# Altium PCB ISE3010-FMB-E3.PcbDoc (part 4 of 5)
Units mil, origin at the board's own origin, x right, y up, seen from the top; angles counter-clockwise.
Board outline 7874.02 x 2362.2 mil, 4 copper layers (Top Layer, MidLayer1, MidLayer2, Bottom Layer), stack 55.6 mil thick; 507 components, 331 nets, 1707 pads, 610 vias.
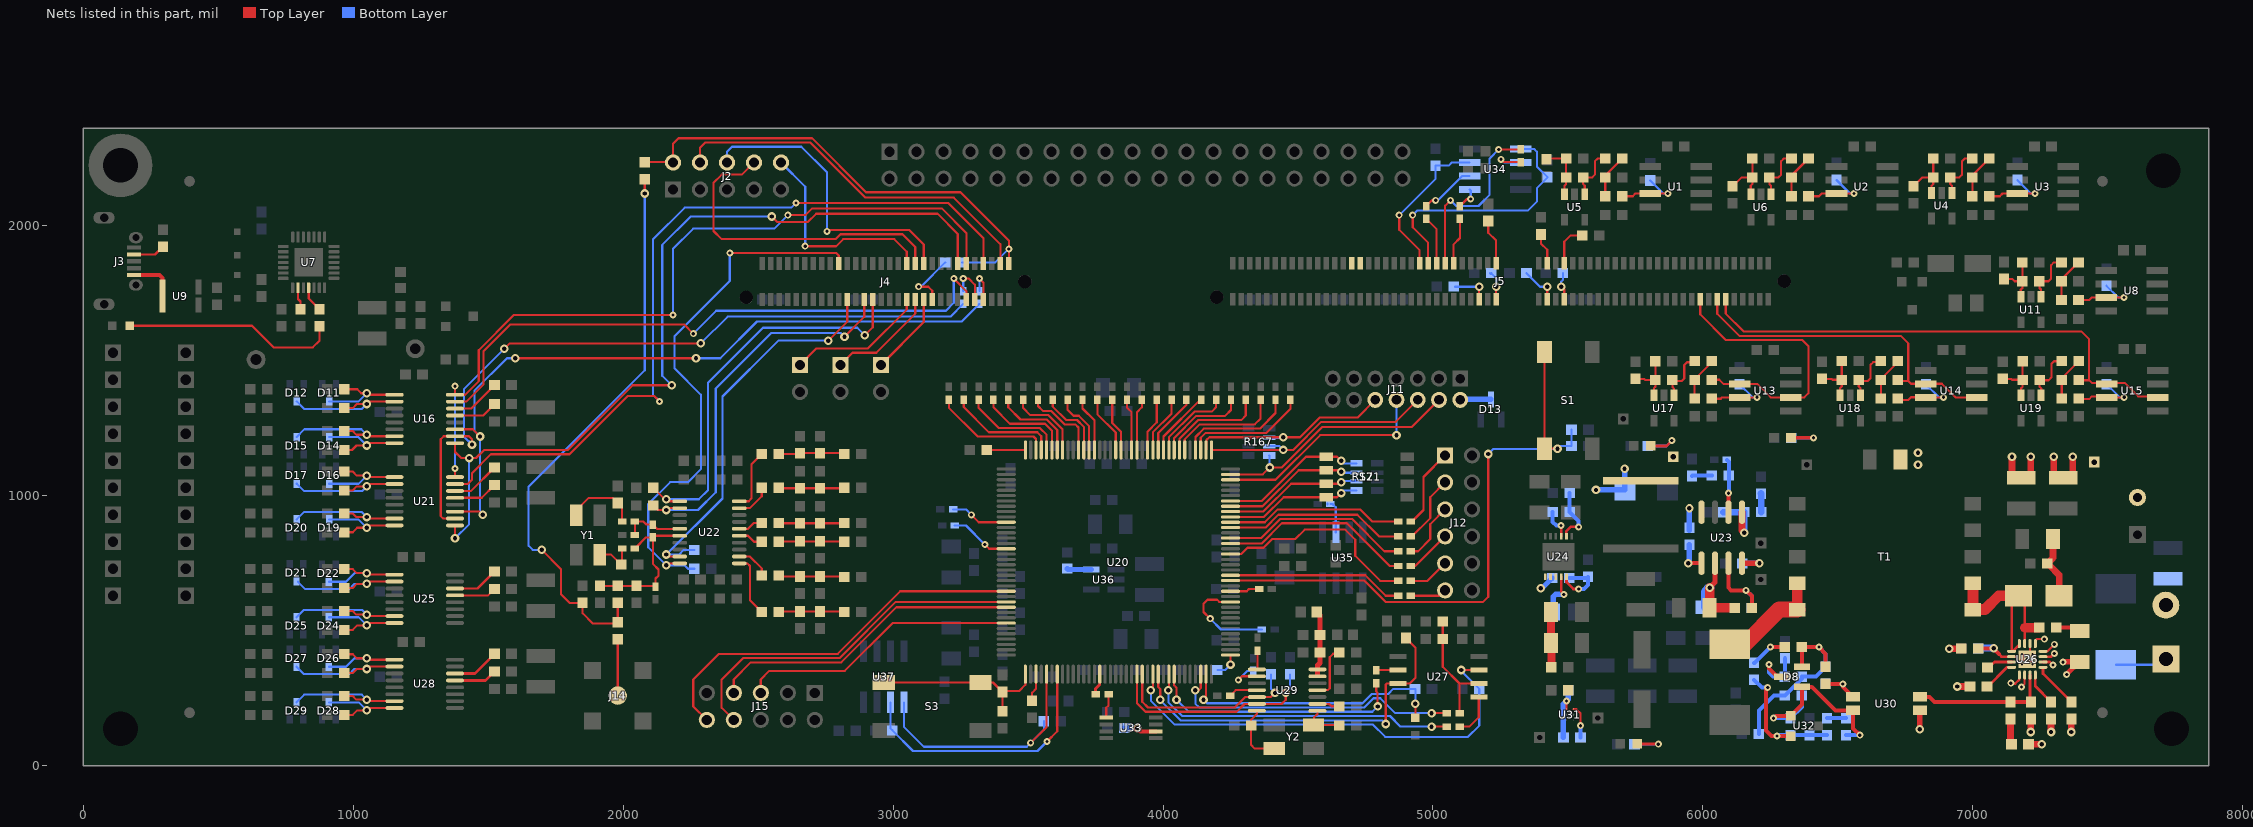
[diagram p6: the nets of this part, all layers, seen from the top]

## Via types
v1: diameter 32, hole 16, Top Layer to Bottom Layer, tented both sides, 495 vias
v2: diameter 26, hole 12, Top Layer to Bottom Layer, tented both sides, 104 vias
v3: diameter 20, hole 8, Top Layer to Bottom Layer, tented both sides, 10 vias
v4: diameter 30, hole 16, Top Layer to Bottom Layer, tented both sides, 1 vias

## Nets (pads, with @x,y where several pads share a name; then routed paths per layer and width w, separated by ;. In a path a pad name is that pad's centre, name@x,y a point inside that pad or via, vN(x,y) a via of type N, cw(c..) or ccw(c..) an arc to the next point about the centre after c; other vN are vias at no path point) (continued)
GND: C41.1 C48.2 C49.2 C50.2 C90.2 C98.2 C103.2 C109.2 C146.2 J13.2 R131.1 R150.2 R151.2 TP5.1 U26.5 U26.6 U26.10 U26.11 U26.12 U26.13 U26.14 U26.17 U30.3 | length 1218.7
  Top Layer w8: v2(7180,292) 7192.09,304.09 U26.6@7192.09,336.46 ; v3(7201.93,394.53) 7211.77,404.37 U26.14@7211.77,452.6 ; U26.13@7232,453.14 7232,464 7238,470 7259,470 7260,469 v2(7265,469) ; U26.12@7260,424.06 7277.06,424.06 7303,450 v2(7302,450)
  Top Layer w9: v2(7141,306) 7143,304 7157,304 7172.4,319.4 U26.5@7172.4,336.46 ; U26.11@7260,404.37 7290.37,404.37 v2(7302,416)
  Top Layer w10: U26.10@7260,384.68 7285.31,384.68 v2(7297,373)
  Top Layer w20: v1(6804.02,135.98) U30.3@6804.02,205 ; v2(7334,384) 7338,384 7338.91,384.91 R131.1@7396,384.91 7392.91,384.91 v2@7348,340
  Top Layer w25: v1(6913,434) 6956.5,434 C90.2@6957.5,435 ; v1(6942,294) C98.2@6990.5,294 ; v1(7145,1145) 7145,1070 7180,1070 C48.2@7180,1067.09 ; C109.2@7206.5,80 v1(7255,80) ; v1(7215,125) C103.2@7215,173.5 ; C48.2@7215,1070 v1(7215,1145) ; v1(7290,125) R150.2@7290,173.5 ; v1(7300,1145) 7300,1070 7335,1070 C49.2@7335,1067.09 ; v1(7365,125) R151.2@7365,173.5 ; C49.2@7370,1070 v1(7370,1145)
  other v1: 6797,1115 6797,1160
  other v2: 7348,338
  other v3: 7182.24,374.84 7221.61,374.84 7182.24,414.21 7221.61,414.21
GPIO1: J2.10 J4.145 | length 797
  Top Layer w8: v2(2674.5,1925) 2789,1925 2815,1951 3004.2,1951 3050.92,1904.28 J4.145@3050.92,1860.93
  Bottom Layer w8: J2.10@2585,2235 2674.5,2145.5 v2(2674.5,1925)
GPIO1_FPGA: J15.7 U20.27 | length 1170.1
  Top Layer w8: J15.7@2410,270 2410,320 2473.2,383.2 2807.89,383.2 3012.21,587.52 U20.27@3419.29,587.52
GPIO2: J2.6 J4.141 | length 1128.8
  Top Layer w8: v2(2755,1980) 2760,1985 3060,1985 3113.91,1931.09 J4.141@3113.91,1860.93
  Bottom Layer w8: J2.6@2385,2235 2385,2275 2403.4,2293.4 2660,2293.4 2755,2198.4 v2(2755,1980)
GPIO2_FPGA: J15.8 U20.26 | length 1341.9
  Top Layer w8: J15.8@2410,170 2365,215 2365,320 2444,399 2801.34,399 3009.55,607.2 U20.26@3419.29,607.2
GPIO3: J2.8 J4.143 | length 1207.9
  Top Layer w8: J2.8@2485,2235 2440,2190 2365,2190 2335,2160 2335,1981 2365,1951 2786.8,1951 2805,1969.2 3035,1969.2 3082.42,1921.78 J4.143@3082.42,1860.93
GPIO3_FPGA: J15.10 U20.24 | length 1465.3
  Top Layer w8: J15.10@2310,170 2260,220 2260,320 2354.8,414.8 2794.8,414.8 3026.57,646.57 U20.24@3419.29,646.57
I2C_SCL: J4.161 R208.2 U22.10 | length 2028.9
  Top Layer w8: v1(2160,742.74) 2167.1,749.84 U22.10@2209.76,749.84 ; v2(2395,1900) 2789.5,1900 2798.95,1890.55 J4.161@2798.95,1860.93
  Bottom Layer w8: R208.2@2263.5,730 2240.02,730 2227.28,742.74 v1(2160,742.74) 2093,809.74 2093,970 2174,1051 2240,1051 2288,1099 2288,1375 2190,1473 2190,1591 2395,1796 v2(2395,1900)
I2C_SCL_2: J5.91
I2C_SCL_FPGA: R203.1 U20.43 U37.6 | length 990.8
  Top Layer w8: v2(3570,90) 3608.27,128.27 U20.43@3608.27,339.49
  Bottom Layer w8: U37.6@2990,235 2990,138.78 R203.1@2997.36,131.42 3073.78,55 3535,55 v2(3570,90)
I2C_SDA: J4.160 R207.2 U22.9 | length 1494.1
  Top Layer w8: v1(2160,782.54) 2167.1,775.43 U22.9@2209.76,775.43 ; v1(2760,1575) 2830.45,1645.45 J4.160@2830.45,1727.07
  Bottom Layer w8: R207.2@2263.5,800 2225,800 2207.54,782.54 v1(2160,782.54) 2368,990.54 2368,1368 2575,1575 v1(2760,1575)
I2C_SDA_2: J5.89
I2C_SDA_FPGA: R201.1 U20.41 U37.5 | length 975.6
  Top Layer w8: v2(3510,85) 3568.9,143.9 U20.41@3568.9,339.49
  Bottom Layer w8: U37.5@3040,235 3040,145 3114.2,70.8 3495.8,70.8 v2(3510,85) 3558.5,133.5 R201.1@3558.5,165
MCU_DAC_ENABLE-1: J4.132 U16.15 | length 2286.6
  Top Layer w8: U16.15@1377.2,1348.98 1418.98,1348.98 1482.2,1412.2 1482.2,1534.86 1582.34,1635 2226,1635 v2(2260,1601) ; v2(3224.93,1805) 3271.39,1758.53 J4.132@3271.39,1727.07
  Bottom Layer w8: v2(2260,1601) 2344.8,1685.8 3195.8,1685.8 3224.93,1714.93 v2(3224.93,1805)
MCU_DAC_ENABLE-2: J4.127 U21.15 | length 2953.9
  Top Layer w8: U21.15@1377.2,1043.98 1423.98,1043.98 1440,1060 1440,1084.2 1510,1154.2 1801.54,1154.2 2017.34,1370 2115,1370 v2(2135,1350) ; v2(2640,2085) 3204.39,2085 3334.39,1955 J4.127@3334.39,1860.93
  Bottom Layer w8: v2(2135,1350) 2110,1375 2110,1950 2227.8,2067.8 2622.8,2067.8 v2(2640,2085)
MCU_DAC_SCK: R165.1 U16.10 U21.10 | length 2685.5
  Top Layer w8: U21.10@1377.2,916.02 1333.03,916.02 1324.06,925 1324.06,1210.08 1335,1221.02 U16.10@1377.2,1221.02 1428.98,1221.02 1440,1210 v1(1440,1190) ; v1(1560,1545) 1580,1565 v1(2288,1565)
  Bottom Layer w8: v1(1440,1190) 1410,1220 1410,1395 v1(1560,1545) ; v1(2288,1565) 2387,1664 3212.62,1664 R165.1@3260,1711.38
MCU_DAC_SDI: R164.1 U16.11 U21.11 | length 2687.8
  Top Layer w8: U21.11@1377.2,941.61 1468.39,941.61 v1(1480,930) ; U16.11@1377.2,1246.61 1443.39,1246.61 v1(1470,1220) ; v1(1600,1510) v1(2270,1510)
  Bottom Layer w8: v1(1480,930) 1470,940 v1(1470,1220) 1448.98,1241.02 1448.98,1388.98 1570,1510 v1(1600,1510) ; v1(2270,1510) 2360,1510 2496,1646 3254.62,1646 R164.1@3320,1711.38
MCU_DAC_SYNC: J4.133 U16.9 U21.9 | length 3156.9
  Top Layer w8: v1(1377.2,842.8) U21.9@1377.2,890.43 ; U16.9@1377.2,1195.43 1377.2,1162.8 1400,1140 v1(1429.32,1140) 1455,1140 1485,1170 1795,1170 2035,1410 v1(2180,1410) ; v1(2550,2035) 2570,2015 2685,2015 2715,2045 3165,2045 3239.9,1970.1 J4.133@3239.9,1860.93
  Bottom Layer w8: v1(1377.2,842.8) 1429.32,894.91 v1(1429.32,1140) ; v1(2180,1410) 2145,1445 2145,1930 2250,2035 v1(2550,2035)
MCU_LDAC: J4.131 U16.16 U21.16 | length 2910.4
  Top Layer w8: U21.16@1377.2,1069.57 v2(1377.2,1101.46) ; v2(1377.2,1406.46) U16.16@1377.2,1374.57 1414.57,1374.57 1465,1425 1465,1540 1595,1670 v2(2185,1670) ; v2(2610,2040) 2675,2040 2700,2065 3180,2065 3271.39,1973.61 J4.131@3271.39,1860.93
  Bottom Layer w8: v2(1377.2,1101.46) v2(1377.2,1406.46) ; v2(2185,1670) 2185,1915 2260,1990 2560,1990 v2(2610,2040)
MCU_SRAM_CS: J5.73 R157.1 U34.1 | length 964.8
  Top Layer w8: v2(4925,2040) 4925,1995 4982.28,1937.72 J5.73@4982.28,1861.93
  Bottom Layer w8: v2(4925,2040) 4942.8,2057.8 5352.8,2057.8 5385,2090 5385,2140.12 R157.1@5425,2180.12 5385,2220.12 5385,2275 5375,2285 U34.1@5325,2285
MCU_SRAM_HOLD: J5.75 R156.1 U34.7 | length 579.6
  Top Layer w8: v2(4875,2040) 4875,1985.79 4950.79,1910 J5.75@4950.79,1861.93
  Bottom Layer w8: v2(4875,2040) 5010,2175 R156.1@5010,2223.5 5058.5,2223.5 5070,2235 U34.7@5136,2235
MCU_SRAM_SCLK: R19.2 U34.6 | length 207.1
  Top Layer w8: R19.2@4975,2073.62 4996.38,2095 v2(5010,2095)
  Bottom Layer w8: v2(5010,2095) 5019,2095 5109,2185 U34.6@5136,2185
MCU_SRAM_SDI: R20.2 U34.5 | length 87.6
  Top Layer w8: R20.2@5100,2073.62 5126.38,2100 v2(5140,2100)
  Bottom Layer w8: U34.5@5136,2135 5140,2131 v2(5140,2100)
MCU_SRAM_SDO: J5.69 R1.2 | length 676.2
  Top Layer w8: J5.69@5045.28,1861.93 5045.28,2075.28 v2(5065,2095) ; v2(5243.62,2283.62) R1.2@5325,2283.62
  Bottom Layer w8: v2(5065,2095) 5086.4,2073.6 5168.6,2073.6 5210,2115 5210,2250 v2(5243.62,2283.62)
NetC6_1: C6.1 R5.1 R15.2 | length 166.1
  Top Layer w8: R15.2@5638.5,2110 C6.1@5638.5,2180 5638.5,2187.01 R5.1@5701.5,2250
NetC7_1: C7.1 R6.1 R16.2 | length 166.1
  Top Layer w8: R16.2@6328.5,2110 C7.1@6328.5,2180 6328.5,2187.01 R6.1@6391.5,2250
NetC8_1: C8.1 R7.1 R17.2 | length 166.1
  Top Layer w8: R17.2@6998.5,2110 C8.1@6998.5,2180 6998.5,2187.01 R7.1@7061.5,2250
NetC16_1: C16.1 R26.1 R28.2 | length 166.1
  Top Layer w8: R28.2@7328.82,1725 C16.1@7328.82,1795 7328.82,1802.01 R26.1@7391.81,1865
NetC29_1: C29.1 R32.1 R69.2 | length 166.1
  Top Layer w8: R69.2@5969.5,1355 5969.5,1425 5969.5,1432.01 R32.1@6032.5,1495
NetC30_1: C30.1 R33.1 R70.2 | length 166.1
  Top Layer w8: R70.2@6659.5,1355.47 6659.5,1425.47 6659.5,1432.48 R33.1@6722.5,1495.47
NetC31_1: C31.1 R34.1 R71.2 | length 166.1
  Top Layer w8: R71.2@7329.5,1358.54 7329.5,1428.54 7329.5,1435.55 R34.1@7392.5,1498.54
NetC42_2: C42.2 R75.2 R76.1 R79.2 | length 244.9
  Top Layer w8: R79.2@2576.5,1155 2651.5,1155 R75.2@2655,1158.5 R76.1@2730,1158.5 2815,1158.5 C42.2@2818.5,1155
NetC55_1: C55.1 R93.1 Y1.3 | length 274.3
  Top Layer w8: Y1.3@1826.69,927.83 1826.69,946.69 1872.5,992.5 1961,992.5 C55.1@1980,973.5 1996.38,957.13 R93.1@1996.38,905
NetC56_2: C56.2 R81.2 R82.1 R85.2 | length 241.1
  Top Layer w8: R85.2@2577.99,1028.5 R81.2@2655,1028.5 R82.1@2730,1028.5 2817.01,1028.5 C56.2@2818.5,1030
NetC60_2: C60.2 R89.2 R90.1 R92.2 | length 243.2
  Top Layer w8: R92.2@2576.5,900 2577.99,898.5 R89.2@2655,898.5 R90.1@2730,898.5 2817.01,898.5 C60.2@2818.5,900
NetC62_2: C62.2 R100.1 R101.2 R102.2 | length 243.2
  Top Layer w8: R102.2@2576.5,830 2577.99,831.5 R100.1@2655,831.5 R101.2@2730,831.5 2817.01,831.5 C62.2@2818.5,830
NetC65_1: C65.1 R104.1 Y1.1 | length 156.8
  Top Layer w8: Y1.1@1913.31,782.17 1955.35,782.17 1992.52,745 C65.1@1993.5,745 1996.38,747.87 R104.1@1996.38,805
NetC67_2: C67.2 D6.1 R98.1 | length 227
  Top Layer w25: C67.2@7276.5,750 7297.09,770.59 R98.1@7297.09,840 ; C67.2@7283.25,743.25 7320,706.5 D6.1@7320,630
NetC69_2: C69.2 R109.2 R110.1 R111.2 | length 244.1
  Top Layer w8: R109.2@2576.5,705 2580,701.5 R110.1@2655,701.5 R111.2@2730,701.5 2817.01,701.5 C69.2@2818.5,700
NetC74_1: C74.1 R95.1 R104.2 R113.2 R115.1 R116.2 U22.6 | length 587.7
  Top Layer w8: R113.2@1915,666.5 C74.1@1980,666.5 R115.1@2050,666.5 2117.13,666.5 R116.2@2120,663.62 2120,693.68 2130.8,704.48 2130.8,727.52 2110,748.32 R95.1@2110,846.38 ; R104.2@2043.62,805 2085,846.38 R95.1@2110,846.38 ; U22.6@2209.76,852.2 2115.83,852.2 R95.1@2110,846.38
NetC74_2: C74.2 R9.1 R114.2 R130.2 | length 2136.6
  Top Layer w8: v1(1698,800) 1770,728 1770,635 1801.5,603.5 R114.2@1850,603.5 1850,565 1887.8,527.2 1975.7,527.2 R130.2@1980,531.5 C74.2@1980,603.5 ; v1(2080,2120) R9.1@2080,2173.5
  Bottom Layer w8: v1(1698,800) 1665,800 1650,815 1650,1035 2080,1465 v1(2080,2120)
NetC78_1: C78.1 R122.2 R182.2 U23.2 | length 346.4
  Top Layer w20: v1(6025,660) 6045,680 U23.2@6045,750.51
  Top Layer w35: v1(6025,660) C78.1@6025,585 R122.2@6118.5,585
  Bottom Layer w35: R182.2@6010,587.09 6010,645 v1(6025,660)
NetC79_1: C79.1 C87.1 R139.1 R181.2 U24.1 U24.2 U24.3 | length 262.6
  Top Layer w30: C79.1@5437.91,570 C87.1@5437.91,455 5438.5,454.41 R139.1@5438.5,365
  Bottom Layer w20: v1(5400,657.99) 5405,657.99 R181.2@5442.01,695
NetC82_2: C82.2 R124.1 R125.2 R126.2 | length 243.2
  Top Layer w8: R126.2@2576.5,570 2577.99,571.5 R124.1@2655,571.5 R125.2@2730,571.5 2817.01,571.5 C82.2@2818.5,570
NetC84_1: C84.1 D6.2 T1.4 T1.5 U26.1 U26.15 U26.16 | length 792.6
  Top Layer w10: U26.16@7172.4,452.6 7172.4,449.4 7149,426 7145.8,426 U26.1@7143.86,424.06 7143.86,603.86 D6.2@7170,630 7192.09,607.91 7192.09,512 U26.15@7192.09,452.6 ; 7215.5,512 7215.5,518.5
  Top Layer w35: 7192.09,512 C84.1@7244,512
  Top Layer w40: T1.4@7000.5,677 T1.5@7000.5,579 7045,579 7096,630 D6.2@7170,630
NetC84_2: C84.2 R131.2 | length 91.9
  Top Layer w15: C84.2@7309.5,512 7383.09,512 R131.2@7396,499.09
NetC86_2: C86.2 C92.2 FB2.2 U29.6 U29.7 | length 238
  Top Layer w20: FB2.2@4569.53,570 4581.5,558.03 C86.2@4581.5,485 4581.5,433.9 C92.2@4572.2,424.61 ; 4572.2,340 U29.7@4572.2,357.09 4572.2,372.2 4581.5,381.5 C92.2@4581.5,420
NetC90_1: C90.1 R186.1 U26.2 | length 197.1
  Top Layer w10: 7097,414 7106.63,404.37 U26.2@7143.86,404.37
  Top Layer w15: C90.1@7020.5,435 7076,435 7097,414
  Bottom Layer w15: R186.1@7020,435 R186.1@7020.5,435 R186.1@7021.5,436 ; v1@7076,435 v1@7080,431
  Bottom Layer w25: R186.1@7021.5,436 v1@7075,436
  other v1: 7078,435
NetC95_1: C95.1 D8.2 R135.1 R191.2 R193.2 R198.2 R204.1 | length 710.7
  Top Layer w15: D8.2@6368.31,366.5 D8.2@6367.4,367.4 6367.4,439.09 R135.1@6366.5,440 v2(6430,440) 6455,415 C95.1@6455,366.5
  Bottom Layer w15: R204.1@6207.5,118 6207.5,204.5 6263,260 R198.2@6303.5,260 6366.5,322.99 R193.2@6366.5,330 6418.5,330 R191.2@6455,366.5 6455,415 v2(6430,440)
NetC95_2: C95.2 R191.1 U30.1 | length 191
  Top Layer w15: C95.2@6455,303.5 v2(6518.5,303.5) 6518.5,292.48 U30.1@6555.98,255
  Bottom Layer w15: R191.1@6455,303.5 v2(6518.5,303.5)
NetC98_1: C98.1 U26.4 | length 129.9
  Top Layer w10: C98.1@7045,290 7052,290 7127,365 U26.4@7143.86,365
NetC101_1: C101.1 R197.1 R205.2 U31.4 | length 222.5
  Top Layer w8: U31.4@5494.58,209.75 v2(5494.58,240)
  Top Layer w10: C101.1@5494.58,273.08 C101.1@5501.5,280
  Bottom Layer w20: R205.2@5483.5,105 5483.5,228.93 v2(5494.58,240) 5501.5,246.92 R197.1@5501.5,280
NetC103_1: C103.1 R149.2 U26.7 U30.4 | length 513.5
  Top Layer w10: C103.1@7208.54,236.5 7211.77,239.72 U26.7@7211.77,336.46
  Top Layer w15: U30.4@6804.02,255 6840,255 6858.5,236.5 R149.2@7140,236.5 C103.1@7208.54,236.5
NetC104_2: C104.2 R144.1 S3.1 S3.2 U20.37 | length 660
  Top Layer w8: S3.1@2965.87,308.58 S3.2@3324.13,308.58 3369.92,308.58 R144.1@3405,273.5 C104.2@3405,201.5 ; R144.1@3405,276.5 3466.5,276.5 3490.16,300.16 U20.37@3490.16,339.49
NetC106_1: C106.1 U29.1 Y2.1 | length 154.7
  Top Layer w8: U29.1@4572.2,203.54 4572.2,192.2 4560,180 4560,152.97 Y2.1@4557.84,150.81 4652.7,150.81 C106.1@4653.5,150
NetC107_1: C107.1 U29.14 Y2.3 | length 227
  Top Layer w8: U29.14@4347.8,203.54 4347.8,192 4326.5,170.7 C107.1@4326.5,150 4326.5,76.97 4340,63.47 4411.44,63.47 Y2.3@4412.17,64.19
NetC109_1: C109.1 R149.1 | length 95
  Top Layer w25: R149.1@7140,173.5 7140,83.5 C109.1@7143.5,80
NetC110_2: C110.2 R17.1 U3.3 | length 258.4
  Top Layer w8: R17.1@7061.5,2110 7100,2110 7110,2120 U3.3@7165,2120 v2(7230,2120)
  Bottom Layer w8: C110.2@7165,2170 7215,2120 v2(7230,2120)
NetC111_2: C111.2 R16.1 U2.3 | length 258.4
  Top Layer w8: R16.1@6391.5,2110 6430,2110 6440,2120 U2.3@6495,2120 v2(6560,2120)
  Bottom Layer w8: C111.2@6495,2170 6545,2120 v2(6560,2120)
NetC112_2: C112.2 R15.1 U1.3 | length 257.7
  Top Layer w8: R15.1@5701.5,2110 5740,2110 5750,2120 U1.3@5805,2120 v2(5870,2120)
  Bottom Layer w8: C112.2@5805,2168.5 5853.5,2120 v2(5870,2120)
NetC113_2: C113.2 R28.1 U8.3 | length 256
  Top Layer w8: R28.1@7391.81,1725 7430.31,1725 7440.31,1735 U8.3@7495,1735 v2(7560.31,1735)
  Bottom Layer w8: C113.2@7495,1778.5 7538.5,1735 v2(7560.31,1735)
NetC120_2: C120.2 R71.1 U15.3 | length 257.7
  Top Layer w8: R71.1@7392.5,1358.54 7431,1358.54 7441,1368.54 U15.3@7496,1368.54 ; U15.3@7496,1365 v2(7561,1365)
  Bottom Layer w8: C120.2@7496,1413.5 7544.5,1365 v2(7561,1365)
NetC121_2: C121.2 R70.1 U14.3 | length 257.7
  Top Layer w8: R70.1@6722.5,1355.47 6761,1355.47 6771,1365.47 U14.3@6826,1365.47 ; U14.3@6826,1365 v2(6891,1365)
  Bottom Layer w8: C121.2@6826,1413.5 6874.5,1365 v2(6891,1365)
NetC122_2: C122.2 R69.1 U13.3 | length 255.7
  Top Layer w8: R69.1@6032.5,1360 6066,1360 6071,1365 U13.3@6136,1365 v2(6201,1365)
  Bottom Layer w8: C122.2@6136,1413.5 6184.5,1365 v2(6201,1365)
NetC127_2: C127.2 R166.1 S1.1 S1.2 U20.87 | length 2315
  Top Layer w8: U20.87@4250,685.94 4746.71,685.94 4826.27,606.39 5185,606.39 5205,626.39 v1(5205,1155) ; S1.1@5411.42,1173.58 S1.1@5412.84,1175 ; S1.2@5412.84,1533.27 S1.1@5412.84,1175 ; v1(5461.42,1174.13) 5460.55,1175 S1.1@5412.84,1175
  Bottom Layer w8: v1(5205,1155) 5224.13,1174.13 v1(5461.42,1174.13) 5472.28,1185 C127.2@5513.5,1185 R166.1@5513.5,1245
NetC130_1: C130.1 C135.1 U23.6 | length 197.9
  Top Layer w15: U23.6@6095,939.49 v2(6095,1010)
  Bottom Layer w15: C130.1@6088.62,1133.5 6096.5,1125.63 C135.1@6096.5,1075 6096.5,1011.5 v2(6095,1010)
NetC135_2: C135.2 R170.2 | length 74.1
  Bottom Layer w15: R170.2@5960,1073.5 5961.5,1075 C135.2@6033.5,1075
NetC139_1: C139.1 D18.1 L1.1 TP4.1 U23.8 | length 273.8
  Bottom Layer w20: v1@5598,1022 D18.1@5711.26,1022 v1@5711.26,1101 ; C139.1@5950,872.5 v4(5950,954)
  other v1: 5604,1022 5710,1101
NetC139_2: C139.2 U23.1 | length 119.3
  Top Layer w15: v1(5945.51,750.51) U23.1@5995,750.51
  Bottom Layer w20: v1(5945.51,750.51) 5950,755 C139.2@5950,818.5
NetC150_1: C150.1 U23.4 | length 128
  Top Layer w20: U23.4@6145,750.51 v1(6209.49,750.51)
  Bottom Layer w20: C150.1@6146.5,750 v1@6210,750
NetC156_1: C156.1 U24.4 | length 169.1
  Top Layer w10: U24.4@5474.84,700.2 5474.84,645.16 v2(5485,635)
  Bottom Layer w20: C156.1@5445,570 5445,626 5454,635 v2(5485,635)
NetC164_1: C164.1 D8.3 R193.1 | length 238.9
  Top Layer w15: v2(6245,375) 6245,360 6275,330 D8.3@6292.6,330
  Bottom Layer w15: v2(6245,375) 6245,345 6260,330 R193.1@6303.5,330 6303.5,397.01 C164.1@6305,398.5
NetC176_1: C176.1 R199.1 | length 70
  Bottom Layer w15: R199.1@6460,176.5 C176.1@6530,176.5
NetC176_2: C176.2 C177.1 D8.1 R198.1 U30.2 U32.1 | length 733.8
  Top Layer w15: v2(6262.01,176.5) 6270.51,185 U32.1@6325,185 6367.4,227.4 D8.1@6367.4,292.6 6403.4,292.6 6491,205 U30.2@6555.98,205 6555.98,139.02 v2(6581.5,113.5)
  Bottom Layer w15: v2(6262.01,176.5) C177.1@6325,176.5 6366.5,217.99 R198.1@6366.5,260 ; C176.2@6530,113.5 v2(6581.5,113.5)
NetC177_2: C177.2 R190.1 R199.2 R200.2 U32.2 | length 509.7
  Top Layer w15: v2(6240,290) 6233.71,283.71 6233.71,131.29 6255,110 v2(6275,110) U32.2@6325,110
  Bottom Layer w15: R190.1@6190,318.5 6218.5,290 v2(6240,290) ; v2(6275,110) 6278.5,113.5 C177.2@6325,113.5 R200.2@6395,113.5 R199.2@6460,113.5
NetD3_2: D3.2 R30.2 | length 799.5
  Top Layer w8: D3.2@172.48,1630 625,1630 705,1550 850,1550 875,1575 R30.2@875,1628.5
NetD4_1: D4.1 R168.1 | length 164.5
  Top Layer w12: D4.1@6327.48,1215 v2(6410,1215)
  Bottom Layer w12: R168.1@6327.99,1215 v2(6410,1215)
NetD5_1: D5.1 R169.1 | length 182.6
  Top Layer w10: D5.1@5807.48,1185 5865,1185 v2(5885,1205)
  Bottom Layer w10: R169.1@5796.5,1185 5865,1185 v2(5885,1205)
NetD7_2: D7.2 T1.6 T1.7 | length 400.7
  Top Layer w40: D7.2@6100,450.49 D7.2@6154.49,450.49 ; T1.6@6349.5,579 T1.7@6349.5,677
  Top Layer w60: D7.2@6154.49,450.49 6283,579 T1.6@6349.5,579
NetD9_2: D9.2 R196.1 U20.71 | length 1017.7
  Top Layer w8: v1(4150,245) 4159.45,254.45 U20.71@4159.45,339.49 ; D9.2@4935,177.48 v1(4935,229.68)
  Bottom Layer w8: v1(4150,245) 4163.4,231.6 4739.26,231.6 4773.46,265.8 4834.2,265.8 4853.4,285 R196.1@4933.5,285 4935,283.5 v1(4935,229.68)
NetD10_1: D10.1 R206.1 | length 166.4
  Top Layer w10: D10.1@5757.48,81 5834,81 v2(5835,80)
  Bottom Layer w10: R206.1@5746.5,80 v2(5835,80)
NetD11_3: D11.3 R68.2 U16.1 | length 346.3
  Top Layer w8: R68.2@966.5,1395 1014.9,1395 ; 1015,1394.9 1030,1379.9 1049.9,1379.9 1055.23,1374.57 U16.1@1152.8,1374.57
  Bottom Layer w8: D11.3@910.71,1350.08 1020.08,1350.08 v1(1050,1380)
NetD12_3: D12.3 R73.2 U16.2 | length 475
  Top Layer w8: R73.2@966.5,1325 998,1325 1013.3,1340.3 1028.2,1340.3 ; 1028.3,1340.2 v1(1050,1340.2) 1058.78,1348.98 U16.2@1152.8,1348.98
  Bottom Layer w8: D12.3@790.71,1350.08 819.21,1321.57 1031.37,1321.57 v1(1050,1340.2)
NetD13_3: D13.3 J11.2 | length 114.5
  Bottom Layer w20: J11.2@5101.22,1355.63 5102.99,1357.4 D13.3@5215,1357.4
NetD14_3: D14.3 R77.2 U16.8 | length 349.2
  Top Layer w8: R77.2@966.5,1170 995.68,1170 1012.28,1186.6 v1(1050,1186.6) 1058.83,1195.43 U16.8@1152.8,1195.43
  Bottom Layer w8: D14.3@910.71,1218.07 1018.53,1218.07 v1(1050,1186.6)
NetD15_3: D15.3 R74.2 U16.7 | length 473.6
  Top Layer w8: R74.2@966.5,1240 998,1240 1011.6,1226.4 v1(1050,1226.4) 1055.38,1221.02 U16.7@1152.8,1221.02
  Bottom Layer w8: D15.3@790.71,1218.07 819.21,1246.57 1029.83,1246.57 v1(1050,1226.4)
NetD16_3: D16.3 R83.2 U21.1 | length 346.4
  Top Layer w8: R83.2@966.5,1090 998,1090 1012.9,1075.1 1027.8,1075.1 1027.9,1075 v1(1050,1075) 1055.43,1069.57 U21.1@1152.8,1069.57
  Bottom Layer w8: D16.3@910.71,1045.08 1020.08,1045.08 v1(1050,1075)
NetD17_3: D17.3 R87.2 U21.2 | length 474.3
  Top Layer w8: R87.2@966.5,1020 998,1020 1013.3,1035.3 1028.2,1035.3 1028.3,1035.2 v1(1050,1035.2) 1058.78,1043.98 U21.2@1152.8,1043.98
  Bottom Layer w8: D17.3@790.71,1045.08 818.26,1017.53 1032.33,1017.53 v1(1050,1035.2)
NetD19_3: D19.3 R96.2 U21.8 | length 349.2
  Top Layer w8: R96.2@966.5,865 998,865 1014.6,881.6 v1(1050,881.6) 1058.83,890.43 U21.8@1152.8,890.43
  Bottom Layer w8: D19.3@910.71,913.07 1018.53,913.07 v1(1050,881.6)
NetD20_3: D20.3 R91.2 U21.7 | length 472.8
  Top Layer w8: R91.2@966.5,935 998,935 1011.5,921.5 1026.4,921.5 1026.5,921.4 v1(1050,921.4) 1055.38,916.02 U21.7@1152.8,916.02
  Bottom Layer w8: D20.3@790.71,913.07 818.26,940.62 1030.78,940.62 v1(1050,921.4)
NetD21_3: D21.3 R117.2 U25.2 | length 475.6
  Top Layer w8: R117.2@966.5,658.54 998,658.54 1013.3,673.84 v1(1050,673.84) 1058.68,682.52 U25.2@1152.8,682.52 ; U25.2@1152.8,680.94 U25.2@1157.7,680.94
  Bottom Layer w8: D21.3@795,682.05 822.55,654.5 985.66,654.5 1005,673.84 v1(1050,673.84)
NetD22_3: D22.3 R107.2 U25.1 | length 347.9
  Top Layer w8: R107.2@966.5,728.54 998,728.54 1012.9,713.64 v1(1050,713.64) 1055.53,708.11 U25.1@1152.8,708.11
  Bottom Layer w8: D22.3@910,682.05 973.4,682.05 1005,713.64 v1(1050,713.64)
NetD23_2: D23.2 J13.1 | length 185.2
  Bottom Layer w8: D23.2@7530,374.51 7714.51,374.51 J13.1@7715,375
NetD24_3: D24.3 R132.2 U25.8 | length 354.1
  Top Layer w8: R132.2@966.5,503.54 998,503.54 1014.7,520.24 v1(1050,520.24) 1058.73,528.98 U25.8@1152.8,528.98 ; U25.8@1152.8,527.34 U25.8@1157.7,527.34
  Bottom Layer w8: D24.3@910,550.04 1020.2,550.04 v1(1050,520.24)
NetD25_3: D25.3 R123.2 U25.7 | length 472.8
  Top Layer w8: R123.2@966.5,573.54 998,573.54 1011.5,560.04 v1(1050,560.04) 1055.48,554.57 U25.7@1152.8,554.57
  Bottom Layer w8: D25.3@790,550.04 817.55,577.59 1032.46,577.59 v1(1050,560.04)
NetD26_3: D26.3 R138.2 U28.1 | length 347.9
  Top Layer w8: R138.2@966.5,413.54 998,413.54 1012.9,398.64 v1(1050,398.64) 1055.53,393.11 U28.1@1152.8,393.11
  Bottom Layer w8: D26.3@910,367.05 973.4,367.05 1005,398.64 v1(1050,398.64)
NetD27_3: D27.3 R143.2 U28.2 | length 480.6
  Top Layer w8: R143.2@966.5,343.54 998,343.54 1013.3,358.84 v1(1050,358.84) 1058.68,367.52 U28.2@1152.8,367.52 ; U28.2@1152.8,365.94 U28.2@1157.7,365.94
  Bottom Layer w8: D27.3@790,367.05 817.55,339.5 985.66,339.5 1005,358.84 v1(1050,358.84)
NetD28_3: D28.3 R153.2 U28.8 | length 354.1
  Top Layer w8: R153.2@966.5,188.54 998,188.54 1014.7,205.24 v1(1050,205.24) 1058.73,213.98 U28.8@1152.8,213.98 ; U28.8@1152.8,212.34 U28.8@1157.7,212.34
  Bottom Layer w8: D28.3@910,235.04 1020.2,235.04 v1(1050,205.24)
NetD29_3: D29.3 R145.2 U28.7 | length 473.6
  Top Layer w8: R145.2@966.5,258.54 998,258.54 1011.5,245.04 v1(1050,245.04) 1055.48,239.57 U28.7@1152.8,239.57
  Bottom Layer w8: D29.3@790,235.04 818.5,263.54 1031.5,263.54 v1(1050,245.04)
NetFB4_1: FB4.1 U36.5 | length 90.3
  Bottom Layer w20: FB4.1@3645,730.47 3648.07,727.4 U36.5@3734,727.4
NetJ3_1: J3.1 U9.1 | length 176.8
  Top Layer w15: J3.1@187.76,1818 282,1818 293.07,1806.93 U9.1@293.07,1740
NetJ3_4: J3.4 R22.2 | length 119.3
  Top Layer w8: J3.4@187.76,1894.5 266,1894.5 R22.2@295,1923.5
NetJ4_128: J4.128 R164.2 | length 130.3
  Top Layer w8: v2(3320,1805) 3334.39,1790.62 J4.128@3334.39,1727.07
  Bottom Layer w8: R164.2@3320,1758.62 v2(3320,1805)
NetJ4_130: J4.130 R165.2 | length 153.8
  Top Layer w8: v2(3260,1805) 3280,1805 3302.89,1782.11 J4.130@3302.89,1727.07
  Bottom Layer w8: R165.2@3260,1758.62 v2(3260,1805)
NetJ4_142: J4.142 J10.1 | length 307.9
  Top Layer w8: J10.1@2955,1485 3113.91,1643.91 J4.142@3113.91,1727.07
NetJ4_144: J4.144 J9.1 | length 408.2
  Top Layer w8: J9.1@2805,1485 2850,1530 2937.42,1530 3082.42,1675 J4.144@3082.42,1727.07
NetJ4_146: J4.146 J8.1 | length 517.9
  Top Layer w8: J8.1@2655,1485 2715.8,1545.8 2906.72,1545.8 3050.92,1690 J4.146@3050.92,1727.07
NetJ5_49: J5.49 R23.2 | length 156.4
  Top Layer w8: J5.49@5486.22,1861.93 5486.22,1941.22 5510,1965 R23.2@5553.5,1965
NetJ5_50: J5.50 R160.1 | length 103.5
  Top Layer w8: v1@5476.93,1775 5486.22,1765.71 J5.50@5486.22,1728.07
  Bottom Layer w8: v1(5475,1775) 5475,1793.5 5481.5,1800 R160.1@5481.5,1825
NetJ5_53: J5.53 R21.2 | length 116.2
  Top Layer w8: R21.2@5400,1968.5 5400,1935 5423.23,1911.77 J5.53@5423.23,1861.93
NetJ5_54: J5.54 R161.1 | length 145.4
  Top Layer w8: J5.54@5423.23,1728.07 5423.23,1774.29 v1(5423.94,1775)
  Bottom Layer w8: R161.1@5346.5,1825 5396.5,1775 v1(5423.94,1775)
NetJ5_57: J5.57 R18.2 | length 168.7
  Top Layer w8: R18.2@5205,2018.5 5205,1975 5234.25,1945.75 J5.57@5234.25,1861.93
NetJ5_58: J5.58 R162.1 | length 108.4
  Top Layer w8: J5.58@5234.25,1728.07 5234.25,1774.29 v1(5234.96,1775)
  Bottom Layer w8: R162.1@5211.5,1825 R162.1@5214,1822.5 ; R162.1@5216.5,1825 5234.96,1806.54 v1(5234.96,1775)
NetJ5_62: J5.62 R163.1 | length 137.7
  Top Layer w8: J5.62@5171.26,1728.07 5171.26,1774.29 v1(5171.97,1775)
  Bottom Layer w8: R163.1@5081.5,1775 v1(5171.97,1775)
NetJ5_67: J5.67 R20.1 | length 174.1
  Top Layer w8: J5.67@5076.77,1861.93 5076.77,1931.77 5100,1955 R20.1@5100,2026.38
NetJ5_71: J5.71 R19.1 | length 180.5
  Top Layer w8: R19.1@4975,2026.38 5013.62,1987.76 5013.62,1862.09 J5.71@5013.78,1861.93
NetJ11_4: J11.4 R167.8 U20.107 | length 931.6
  Top Layer w8: U20.107@4250,1079.65 4369.34,1079.65 v1(4395,1105.31) 4440,1105.31 4589.63,1254.94 4921.79,1254.94 J11.4@5022.48,1355.63
  Bottom Layer w8: R167.8@4393.5,1149.5 4395,1148 v1(4395,1105.31)
NetJ11_6: J11.6 R167.6 U20.109 | length 898.8
  Top Layer w8: U20.109@4179.13,1170.2 v1(4445,1170.2) 4482.54,1170.2 4586.54,1274.2 4862.31,1274.2 J11.6@4943.74,1355.63
  Bottom Layer w8: R167.6@4393.5,1184.5 4430.7,1184.5 v1(4445,1170.2)
NetJ11_8: J11.8 U20.106 | length 814
  Top Layer w8: U20.106@4250,1059.96 4416.99,1059.96 4582.03,1225 v1(4865,1225)
  Bottom Layer w8: v1(4865,1225) J11.8@4865,1355.63
NetJ11_10: J11.10 R167.4 U20.110 | length 776.4
  Top Layer w8: U20.110@4159.45,1170.2 4161.43,1172.17 4161.43,1207.06 4171.8,1217.43 v1(4445,1217.43) 4507.43,1217.43 4580,1290 4720.63,1290 J11.10@4786.26,1355.63
  Bottom Layer w8: R167.4@4393.5,1215.5 4438.07,1215.5 4440,1217.43 v1(4445,1217.43)
NetJ14_1: J14.1 R130.1 | length 208.5
  Top Layer w8: J14.1@1980,260 R130.1@1980,468.5
NetR1_1: R1.1 U34.2 | length 155.4
  Top Layer w8: v2(5252,2247) 5262.62,2236.38 R1.1@5325,2236.38
  Bottom Layer w8: v2(5252,2247) 5264,2235 U34.2@5325,2235
NetR2_1: R2.1 R8.1 R10.1 U5.3 | length 210.2
  Top Layer w8: R8.1@5420,2246.5 5423.5,2250 R2.1@5493.5,2250 R10.1@5493.5,2180 5493.5,2155.3 5487.6,2149.4 U5.3@5487.6,2117.24
NetR3_1: R3.1 R11.1 R13.1 U6.3 | length 222.6
  Top Layer w8: R13.1@6110,2146.5 6143.5,2180 R11.1@6183.5,2180 ; U6.3@6177.6,2117.24 6177.6,2149.4 6183.5,2155.3 R11.1@6183.5,2180 ; R3.1@6183.5,2250 R11.1@6183.5,2180
NetR4_1: R4.1 R12.1 R14.1 U4.3 | length 222.6
  Top Layer w8: R14.1@6780,2146.5 6813.5,2180 R12.1@6853.5,2180 ; U4.3@6847.6,2117.24 6847.6,2149.4 6853.5,2155.3 R12.1@6853.5,2180 ; R4.1@6853.5,2250 R12.1@6853.5,2180
NetR5_2: R5.2 R10.2 U5.1 | length 205.5
  Top Layer w8: U5.1@5562.4,2117.24 5562.4,2149.4 5556.5,2155.3 R10.2@5556.5,2180 5590,2180 5600,2190 5600,2239.95 5610.05,2250 R5.2@5638.5,2250
NetR6_2: R6.2 R11.2 U6.1 | length 205.5
  Top Layer w8: U6.1@6252.4,2117.24 6252.4,2149.4 6246.5,2155.3 R11.2@6246.5,2180 6280,2180 6290,2190 6290,2239.95 6300.05,2250 R6.2@6328.5,2250
NetR7_2: R7.2 R12.2 U4.1 | length 205.5
  Top Layer w8: U4.1@6922.4,2117.24 6922.4,2149.4 6916.5,2155.3 R12.2@6916.5,2180 6950,2180 6960,2190 6960,2239.95 6970.05,2250 R7.2@6998.5,2250
NetR24_1: R24.1 R25.1 R27.1 U11.3 | length 207.5
  Top Layer w8: R24.1@7115,1803.5 7146.5,1803.5 7155,1795 R27.1@7183.82,1795 ; U11.3@7177.91,1732.24 7177.91,1764.4 7183.82,1770.3 R27.1@7183.82,1795 ; R25.1@7183.82,1865 R27.1@7183.82,1795
NetR26_2: R26.2 R27.2 U11.1 | length 205.5
  Top Layer w8: U11.1@7252.72,1732.24 7252.72,1764.4 7246.81,1770.3 R27.2@7246.81,1795 7280.31,1795 7290.31,1805 7290.31,1854.95 7300.36,1865 R26.2@7328.82,1865
NetR29_1: R29.1 U7.9 | length 83.4
  Top Layer w8: U7.9@795.6,1771 795.6,1729.4 805,1720 R29.1@805,1691.5
NetR30_1: R30.1 U7.11 | length 96.1
  Top Layer w8: U7.11@835,1771 835,1731.5 R30.1@875,1691.5
NetR31_1: R31.1 R38.1 R41.1 U18.3 | length 210.2
  Top Layer w8: R38.1@6441,1433.5 6477.5,1433.5 6481,1430 R41.1@6514.5,1430 ; U18.3@6508.6,1362.72 6508.6,1399.4 6514.5,1405.3 R41.1@6514.5,1430 ; R31.1@6514.5,1495.47 R41.1@6514.5,1430
NetR32_2: R32.2 R42.2 U17.1 | length 205.5
  Top Layer w8: U17.1@5893.4,1362.24 5893.4,1397.23 5887.5,1403.14 5887.5,1425 5921,1425 5931,1435 5931,1484.95 5941.05,1495 R32.2@5969.5,1495
NetR33_2: R33.2 R41.2 U18.1 | length 205.5
  Top Layer w8: U18.1@6583.4,1362.72 6583.4,1399.4 6577.5,1405.3 6577.5,1425.47 6611,1425.47 6621,1435.47 6621,1485.42 6631.05,1495.47 R33.2@6659.5,1495.47
NetR34_2: R34.2 R40.2 U19.1 | length 205.5
  Top Layer w8: U19.1@7253.4,1365.79 7253.4,1397.94 7247.5,1403.85 7247.5,1428.54 7281,1428.54 7291,1438.54 7291,1488.49 7301.05,1498.54 R34.2@7329.5,1498.54
NetR35_1: R35.1 R37.1 R42.1 U17.3 | length 209.8
  Top Layer w8: R37.1@5751,1433.5 5782.5,1433.5 5787.3,1428.7 R42.1@5823.64,1428.7 ; U17.3@5818.6,1362.24 5818.6,1398.97 5824.5,1404.87 R35.1@5824.5,1495
NetR36_1: R36.1 R39.1 R40.1 U19.3 | length 210.8
  Top Layer w8: R39.1@7111,1433.5 7142.5,1433.5 7146,1430 7183.05,1430 R40.1@7184.5,1428.54 ; U19.3@7178.6,1365.79 7178.6,1397.94 7184.5,1403.85 R40.1@7184.5,1428.54 ; R36.1@7184.5,1498.54 R40.1@7184.5,1430 R40.1@7184.5,1428.54
NetR43_1: R43.1 U16.14 | length 182.2
  Top Layer w8: U16.14@1377.2,1323.39 1436.89,1323.39 R43.1@1523.5,1410
NetR44_2: R44.2 U20.142 | length 440.6
  Top Layer w8: R44.2@3206.81,1356.38 3206.81,1327 3313.81,1220 3520,1220 3529.53,1210.47 U20.142@3529.53,1170.2
NetR45_2: R45.2 U20.141 | length 410.2
  Top Layer w8: R45.2@3261.81,1356.38 3261.81,1328.98 3354.99,1235.8 3534.2,1235.8 3549.21,1220.79 U20.141@3549.21,1170.2
NetR46_2: R46.2 U20.140 | length 379.9
  Top Layer w8: R46.2@3316.81,1356.38 3316.81,1325.79 3391,1251.6 3543.4,1251.6 3568.9,1226.1 U20.140@3568.9,1170.2
NetR47_2: R47.2 U20.139 | length 352.1
  Top Layer w8: R47.2@3371.81,1356.38 3371.81,1328.19 3432.6,1267.4 3562.6,1267.4 3588.58,1241.42 U20.139@3588.58,1170.2
NetR48_2: R48.2 U20.138 | length 318.4
  Top Layer w8: R48.2@3426.81,1356.38 3426.81,1328.19 3471.8,1283.2 3569.14,1283.2 3608.27,1244.08 U20.138@3608.27,1170.2
NetR49_2: R49.2 U20.137 | length 286
  Top Layer w8: R49.2@3481.81,1356.38 3481.81,1325.79 3508.6,1299 3575.69,1299 3627.95,1246.74 U20.137@3627.95,1170.2
NetR50_2: R50.2 U20.134 | length 289.5
  Top Layer w8: R50.2@3536.81,1356.38 3536.81,1332.99 3555,1314.8 3585.2,1314.8 3635,1265 3675,1265 3687.01,1252.99 3687.01,1220 U20.134@3687.01,1170.2
NetR51_2: R51.2 U20.133 | length 257.2
  Top Layer w8: R51.2@3591.81,1356.38 3591.81,1330.53 3641.54,1280.8 3681.54,1280.8 3706.69,1255.65 U20.133@3706.69,1170.2
NetR52_2: R52.2 U20.132 | length 230.7
  Top Layer w8: R52.2@3646.81,1356.38 3646.81,1318.19 3668.4,1296.6 3688.09,1296.6 3726.38,1258.31 U20.132@3726.38,1170.2
NetR53_2: R53.2 U20.131 | length 204.5
  Top Layer w8: R53.2@3701.81,1356.38 3701.81,1323.98 3746.06,1279.72 U20.131@3746.06,1170.2
NetR54_2: R54.2 U20.127 | length 214.3
  Top Layer w8: R54.2@3756.81,1356.38 3756.81,1302.5 3824.8,1234.51 U20.127@3824.8,1170.2
NetR55_2: R55.2 U20.126 | length 199.7
  Top Layer w8: R55.2@3811.81,1356.38 3811.81,1269.85 3844.49,1237.17 U20.126@3844.49,1170.2
NetR56_2: R56.2 U20.124 | length 193.2
  Top Layer w8: R56.2@3866.81,1356.38 3866.81,1327.05 3883.86,1310 U20.124@3883.86,1170.2
NetR57_2: R57.2 U20.123 | length 193.7
  Top Layer w8: U20.123@3903.54,1170.2 3903.54,1310 3921.81,1328.27 R57.2@3921.81,1356.38
NetR58_2: R58.2 U20.121 | length 200.2
  Top Layer w8: U20.121@3942.91,1170.2 3942.91,1238.39 3976.81,1272.29 R58.2@3976.81,1356.38
NetR59_2: R59.2 U20.120 | length 214.9
  Top Layer w8: U20.120@3962.6,1170.2 3962.6,1235.73 4031.81,1304.94 R59.2@4031.81,1356.38
NetR60_2: R60.2 U20.119 | length 229.5
  Top Layer w8: U20.119@3982.28,1170.2 3982.28,1233.07 4086.81,1337.6 R60.2@4086.81,1356.38
NetR61_2: R61.2 U20.118 | length 246.1
  Top Layer w8: U20.118@4001.97,1170.2 4001.97,1219.93 4138.42,1356.38 R61.2@4141.81,1356.38
NetR62_2: R62.2 U20.117 | length 295.9
  Top Layer w8: U20.117@4021.65,1170.2 4021.65,1217.27 4116.62,1312.23 4180,1312.23 4196.81,1329.04 R62.2@4196.81,1356.38
NetR63_2: R63.2 U20.116 | length 335.9
  Top Layer w8: U20.116@4041.34,1170.2 4041.34,1214.61 4123.16,1296.43 4230,1296.43 4251.81,1318.24 R63.2@4251.81,1356.38
NetR64_2: R64.2 U20.115 | length 381.9
  Top Layer w8: U20.115@4061.02,1170.2 4061.02,1211.95 4129.7,1280.63 4290,1280.63 4306.81,1297.44 R64.2@4306.81,1356.38
NetR65_2: R65.2 U20.114 | length 422
  Top Layer w8: U20.114@4080.71,1170.2 4080.71,1209.29 4136.25,1264.83 4340,1264.83 4361.81,1286.64 R65.2@4361.81,1356.38
NetR66_2: R66.2 U20.112 | length 430.8
  Top Layer w8: U20.112@4120.08,1170.2 4120.08,1217.9 4151.21,1249.03 4359.03,1249.03 4416.81,1306.81 R66.2@4416.81,1356.38
NetR67_2: R67.2 U20.111 | length 455.8
  Top Layer w8: U20.111@4139.76,1170.2 4139.76,1215.24 4157.76,1233.23 4383.23,1233.23 4471.81,1321.81 R67.2@4471.81,1356.38
NetR72_1: R72.1 U16.13 | length 163.8
  Top Layer w8: U16.13@1377.2,1297.8 1481.3,1297.8 R72.1@1523.5,1340
NetR78_1: R78.1 U20.144 | length 143.7
  Top Layer w8: R78.1@3346.5,1170 3346.69,1170.2 U20.144@3490.16,1170.2
NetR79_1: R79.1 U22.20 | length 229.8
  Top Layer w8: U22.20@2430.24,980.16 2465.16,980.16 2475,990 2475,1116.5 R79.1@2513.5,1155
NetR80_1: R80.1 U21.14 | length 182.2
  Top Layer w8: U21.14@1377.2,1018.39 1436.89,1018.39 R80.1@1523.5,1105
NetR84_1: R84.1 U21.13 | length 165.9
  Top Layer w8: U21.13@1377.2,992.8 1476.3,992.8 R84.1@1523.5,1040
NetR85_1: R85.1 U22.19 | length 133
  Top Layer w8: U22.19@2430.24,954.57 2469.57,954.57 2513.5,998.5 R85.1@2513.5,1030
NetR92_1: R92.1 U22.16 | length 92.5
  Top Layer w8: U22.16@2430.24,877.8 2462.8,877.8 2485,900 R92.1@2513.5,900
NetR93_2: R93.2 R95.2 R97.2 U22.5 | length 227.4
  Top Layer w8: R97.2@2043.62,855 R93.2@2043.62,905 2075,905 2086.38,893.62 R95.2@2110,893.62 2125.83,877.8 U22.5@2209.76,877.8
NetR94_2: R94.2 U20.98 | length 659.7
  Top Layer w8: U20.98@4250,902.48 4377.48,902.48 4425,950 4730,950 4775,905 R94.2@4871.38,905
NetR99_2: R99.2 U20.97 | length 674.1
  Top Layer w8: U20.97@4250,882.79 4380.14,882.79 4427.34,930 4720,930 4800,850 R99.2@4871.38,850
NetR102_1: R102.1 U22.15 | length 92.5
  Top Layer w8: U22.15@2430.24,852.2 2462.8,852.2 2485,830 R102.1@2513.5,830
NetR105_2: R105.2 U20.95 | length 700.1
  Top Layer w8: U20.95@4250,843.42 4363.11,843.42 4433.89,914.2 4700.8,914.2 4820,795 R105.2@4871.38,795
NetR106_2: R106.2 U20.94 | length 717.9
  Top Layer w8: U20.94@4250,823.74 4365.77,823.74 4440.43,898.4 4681.6,898.4 4840,740 R106.2@4871.38,740
NetR108_1: R108.1 U25.14 | length 172.4
  Top Layer w8: U25.14@1377.2,656.93 1460.43,656.93 R108.1@1523.5,720
NetR109_1: R109.1 U22.12 | length 128
  Top Layer w8: U22.12@2430.24,775.43 2469.57,775.43 2513.5,731.5 R109.1@2513.5,705
NetR112_2: R112.2 U20.92 | length 772.8
  Top Layer w8: U20.92@4250,784.37 4289.37,784.37 4312.94,807.94 4372.32,807.94 4404.38,840 4490,840 4525,875 4675,875 4712.2,837.8 4712.2,777.8 4805,685 R112.2@4871.38,685
NetR118_1: R118.1 U25.13 | length 156.1
  Top Layer w8: U25.13@1377.2,631.34 1499.84,631.34 R118.1@1523.5,655
NetR119_2: R119.2 U20.85 | length 109.9
  Top Layer w8: U20.85@4250,646.57 4310,646.57 4318.43,655 R119.2@4356.38,655
NetR120_2: R120.2 U20.88 | length 652.7
  Top Layer w8: U20.88@4250,705.63 4749.37,705.63 4825,630 R120.2@4871.38,630
NetR122_1: R122.1 R184.2 U23.3 | length 307.5
  Top Layer w15: U23.3@6095,750.51 6095,660 6105,650 v2(6160,650) 6181.5,628.5 R122.1@6181.5,585
  Bottom Layer w15: v2(6160,650) 6181.5,628.5 R184.2@6181.5,585
NetR126_1: R126.1 U22.11 | length 231.9
  Top Layer w8: U22.11@2430.24,749.84 2460.16,749.84 2470,740 2470,613.5 R126.1@2513.5,570
NetR128_2: R128.2 U20.62 U27.3 | length 1399.3
  Top Layer w8: U20.62@3982.28,339.49 3982.28,292.03 3990,284.32 v1(3990,245) ; v1(4825,155) 4825,259.68 4825,300 4829.68,304.68 U27.3@4870,304.68 4914.68,304.68 4935,325 4935,438.5 R128.2@4900,473.5
  Bottom Layer w8: v1(3990,245) 3990,243.34 4064.94,168.4 4811.6,168.4 v1(4825,155)
NetR129_1: R129.1 R134.2 R154.2 U27.6 | length 437.1
  Top Layer w8: R129.1@5036.5,535 R134.2@5036.5,470 5036.5,366.81 5098.62,304.68 ; R154.2@5098.62,195 5098.62,304.68 ; U27.6@5170,304.68 5098.62,304.68
NetR133_1: R133.1 U29.8 | length 70.2
  Top Layer w8: U29.8@4347.8,357.09 4350,359.29 R133.1@4350,426.38
NetR135_2: R135.2 R190.2 | length 137.7
  Top Layer w15: v2(6250,440) R135.2@6303.5,440
  Bottom Layer w15: R190.2@6190,381.5 6191.5,381.5 v2(6250,440)
NetR136_1: R136.1 U29.4 | length 214.6
  Top Layer w8: U29.4@4572.2,280.32 4610.32,280.32 4617.47,287.47 4617.47,402.47 4630.32,415.32 R136.1@4663.5,415.32
NetR137_1: R137.1 U28.14 | length 176.6
  Top Layer w10: U28.14@1377.2,341.93 1450.43,341.93 R137.1@1523.5,415
NetR140_1: R140.1 U26.3 | length 97.5
  Top Layer w10: R140.1@7054.5,365 7061,365 7080.69,384.68 U26.3@7143.86,384.68
NetR141_1: R141.1 U27.2 | length 80.4
  Top Layer w8: R141.1@4790,353.62 4791.06,354.68 U27.2@4870,354.68
NetR141_2: R141.2 U20.65 | length 958.4
  Top Layer w8: U20.65@4041.34,339.49 4041.34,297.98 4050,289.32 v1(4050,245) ; R141.2@4790,306.38 4790,275 4795,270 v1(4795,220)
  Bottom Layer w8: v1(4050,245) 4095,200 4775,200 v1(4795,220)
NetR142_1: R142.1 U28.13 | length 160.2
  Top Layer w10: U28.13@1377.2,316.34 1489.84,316.34 R142.1@1523.5,350
NetR146_1: R146.1 U20.51 | length 81.6
  Top Layer w10: R146.1@3751.38,265 3750,266.38 3750,285.5 3765.75,301.25 U20.51@3765.75,339.49
NetR146_2: R146.2 U33.1 | length 89.7
  Top Layer w8: U33.1@3789.8,179 3789.8,214.8 3798.62,223.62 R146.2@3798.62,265
NetR147_1: R147.1 U29.11 | length 107.6
  Top Layer w8: R147.1@4248.62,260 4268.94,280.32 U29.11@4347.8,280.32
NetR148_1: R148.1 U20.39 | length 104
  Top Layer w8: R148.1@3515,241.5 3515,270.47 3529.53,285 U20.39@3529.53,339.49
NetR150_1: R150.1 U26.8 | length 124.2
  Top Layer w10: U26.8@7231.46,336.46 7231.46,295.04 R150.1@7290,236.5
NetR151_1: R151.1 U26.9 | length 172
  Top Layer w10: U26.9@7260,365 7260,341.5 R151.1@7365,236.5
NetR152_1: R152.1 U29.2 | length 85
  Top Layer w8: U29.2@4572.2,229.13 4615.16,229.13 4623.98,220.32 R152.1@4653.5,220.32
NetR154_1: R154.1 U20.70 | length 1099
  Top Layer w8: v1(4120,280) 4132.13,280 4139.77,287.64 U20.70@4139.76,339.49 ; v1(4995,195) R154.1@5051.38,195
  Bottom Layer w8: v1(4120,280) 4120,230 4134.2,215.8 4745.8,215.8 4780,250 4805,250 4860,195 v1(4995,195)
NetR155_1: R155.1 U27.5 | length 160.6
  Top Layer w8: R155.1@5098.62,145 5135,145 5170,180 U27.5@5170,254.68
NetR155_2: R155.2 U20.64 | length 1166.1
  Top Layer w8: v1@4021.65,286.65 U20.64@4021.65,339.49 ; v1(4995,145) R155.2@5051.38,145
  Bottom Layer w8: v1(4020,280) 4020,235.68 4071.48,184.2 4840.8,184.2 4880,145 v1(4995,145)
NetR171_1: R171.1 S2.1 U20.102 | length 544.5
  Top Layer w8: U20.102@4250,981.22 4366.22,981.22 4530,1145 S2.1@4605,1145 4644.7,1145 v1(4660,1129.7)
  Bottom Layer w8: v1(4660,1129.7) 4669.2,1120.5 R171.1@4716.5,1120.5
NetR171_3: R171.3 S2.2 U20.101 | length 525.7
  Top Layer w8: U20.101@4250,961.54 4368.88,961.54 4502.34,1095 S2.2@4605,1095 4654.9,1095 v1(4660,1089.9)
  Bottom Layer w8: v1(4660,1089.9) 4664.4,1085.5 R171.3@4716.5,1085.5
NetR171_5: R171.5 S2.3 U20.100 | length 513.2
  Top Layer w8: U20.100@4250,941.85 4371.54,941.85 4474.69,1045 S2.3@4605,1045 4654.9,1045 v1(4660,1050.1)
  Bottom Layer w8: v1(4660,1050.1) 4664.4,1054.5 R171.5@4716.5,1054.5
NetR171_7: R171.7 S2.4 U20.99 | length 506.8
  Top Layer w8: U20.99@4250,922.16 4374.2,922.16 4447.03,995 S2.4@4605,995 4644.7,995 v1(4660,1010.3)
  Bottom Layer w8: v1(4660,1010.3) 4669.2,1019.5 R171.7@4716.5,1019.5
NetR172_1: R172.1 R177.2 | length 69.1
  Bottom Layer w25: R172.1@6215,1008.5 6216.5,1007.01 R177.2@6216.5,940
NetR173_2: R173.2 R176.1 U24.8 | length 210.5
  Top Layer w9: U24.8@5494.53,849.8 5494.53,869.53 5510,885 v2(5540,885)
  Bottom Layer w15: R173.2@5506.5,1010 R176.1@5506.5,940 5540,906.5 v2(5540,885)
NetR174_1: R174.1 U35.2 | length 121.8
  Bottom Layer w8: R174.1@4610,967.5 R174.1@4610,971.38 ; R174.1@4620,970 4628,970 4640,958 U35.2@4640,865
NetR175_2: R175.2 U20.11 | length 216.7
  Top Layer w8: v2(3290,930) 3317.52,902.48 U20.11@3419.29,902.48
  Bottom Layer w8: R175.2@3222.24,950 3270,950 v2(3290,930)
NetR176_2: R176.2 U24.9 | length 113.5
  Top Layer w9: U24.9@5474.84,849.8 v2(5474.84,889.84)
  Bottom Layer w15: R176.2@5443.5,940 5443.5,903.5 5457.16,889.84 v2(5474.84,889.84)
NetR177_1: R177.1 R178.2 U23.5 | length 233.2
  Top Layer w25: U23.5@6145,939.49 6145,872.01 v1(6153.5,863.5)
  Bottom Layer w25: R178.2@6076.5,939.49 6152.99,939.49 R177.1@6153.5,940 v1(6153.5,863.5)
NetR179_2: R179.2 U20.16 | length 226.3
  Top Layer w8: v2(3340,820) 3355.95,804.05 U20.16@3419.29,804.05
  Bottom Layer w8: R179.2@3228.62,890 3270,890 v2(3340,820)
NetR180_2: R180.2 R181.1 U24.5 | length 219
  Top Layer w10: U24.5@5494.53,700.2 5494.53,680.47 5520,655 v2(5540,655)
  Bottom Layer w15: R181.1@5505,695 5570,695 R180.2@5575,700 5575,670 5560,655 v2(5540,655)
NetR185_2: R185.2 U20.83 | length 382.7
  Top Layer w8: v2(4175,545) 4150,570 4150,600 4165,615 4200,615 4207.8,607.2 U20.83@4250,607.2
  Bottom Layer w8: v2(4175,545) 4215,505 R185.2@4366.38,505
NetR187_1: R187.1 U20.58 U29.13 | length 790.9
  Top Layer w8: U20.58@3903.54,339.49 3903.54,231.46 3935,200 4272.66,200 4301.79,229.13 U29.13@4347.8,229.13 4439.13,229.13 4454.8,244.8 4454.8,269.8 v1(4455,270)
  Bottom Layer w8: v1(4455,270) 4470,285 R187.1@4470,338.5
NetR188_1: R188.1 U20.59 U29.12 | length 700.3
  Top Layer w8: U20.59@3923.23,339.49 3923.23,236.77 3944.2,215.8 4266.11,215.8 4305.04,254.73 U29.12@4347.8,254.73 4399.73,254.73 v1(4415,270)
  Bottom Layer w8: R188.1@4400,338.5 4400,285 v1(4415,270)
NetR189_1: R189.1 U29.9 | length 144.2
  Top Layer w8: v2(4279,318) 4292.5,331.5 U29.9@4347.8,331.5
  Bottom Layer w8: v2(4279,318) 4312.38,351.38 R189.1@4335,351.38
NetR192_2: R192.2 U20.73 | length 92.1
  Top Layer w8: v1(4250,375) U20.73@4250,410.35
  Bottom Layer w8: R192.2@4201.5,355 4230,355 v1(4250,375)
NetR195_2: R195.2 U20.61 U27.7 | length 1738.1
  Top Layer w8: U20.61@3962.6,339.49 3962.6,272.6 3960.2,275 v1@3960,275 ; v1(5105.32,354.68) U27.7@5170,354.68 ; v1@3955,275 v1@3960,275 ; v1@3955,275 v1@3957.5,277.5 ; v1@3955,275 v1(3955,280) ; v1@3955,275 3960,270 v1@3960,275 ; v1(3955,280) v1@3957.5,277.5 ; v1(3955,280) 3960,280 v1@3957.5,277.5 ; v1@3957.5,277.5 v1@3960,275
  Bottom Layer w8: v1(3955,280) 3955,240.68 4043.08,152.6 4778.08,152.6 4823.48,107.2 5130,107.2 5171.5,148.7 R195.2@5171.5,285 5105.32,351.18 v1(5105.32,354.68)
NetR202_2: R202.2 U33.6 | length 122
  Top Layer w15: v1(3905,140) 3917.2,127.8 U33.6@3973.4,127.8
  Bottom Layer w20: R202.2@3856.5,140 v1(3905,140)
NetR205_1: R205.1 U31.3 | length 121.7
  Top Layer w8: U31.3@5520.58,209.75 5531.25,209.75 5546.5,194.5 v2(5546.5,148.5)
  Bottom Layer w15: R205.1@5546.5,105 v2(5546.5,148.5)
PH_U_ADCIN: C31.2 J5.12 U15.2 U15.6 | length 1907.6
  Top Layer w8: J5.12@6084.65,1728.07 6084.65,1675 6150.34,1609.3 7401.7,1609.3 7431,1580 7431,1428.54 ; C31.2@7392.5,1428.54 7431,1428.54 ; U15.6@7685,1368.54 7612.46,1368.54 7562.46,1418.54 7441,1418.54 7431,1428.54
PH_V_ADCIN: C29.2 J5.18 U13.2 U13.6 | length 1071.7
  Top Layer w8: J5.18@5990.16,1728.07 5990.16,1672.84 6086,1577 6369.32,1577 6391,1555.32 6391,1380 6376,1365 U13.6@6325,1365 6251,1365 6201,1415 U13.2@6136,1415 6076,1415 6061,1430 C29.2@6032.5,1430
PH_W_ADCIN: C30.2 J5.14 U14.2 U14.6 | length 1264.5
  Top Layer w8: J5.14@6053.15,1728.07 6053.15,1674.96 6135.31,1592.8 6733.2,1592.8 6761,1565 6761,1425.47 ; C30.2@6722.97,1425 6722.5,1425.47 6761,1425.47 ; U14.6@7015,1365.47 7014.53,1365 6936,1365 6885.53,1415.47 6771,1415.47 6761,1425.47
PWM_1: J12.1 R94.1 | length 299.7
  Top Layer w8: R94.1@4918.62,905 4922.56,905 4965,947.44 4965,1070 J12.1@5045,1150
PWM_2: J12.3 R99.1 | length 254.6
  Top Layer w8: R99.1@4918.62,850 4922.5,850 4990,917.5 4990,995 J12.3@5045,1050
PWM_3: J12.5 R105.1 | length 222.8
  Top Layer w8: R105.1@4918.62,795 4945,795 4990,840 4990,895 J12.5@5045,950
PWM_4: J12.7 R106.1 | length 171.9
  Top Layer w8: R106.1@4918.62,740 4935,740 J12.7@5045,850
PWM_5: J12.9 R112.1 | length 153.3
  Top Layer w8: R112.1@4918.62,685 4980,685 J12.9@5045,750
PWM_6: J12.11 R120.1 | length 134.7
  Top Layer w8: R120.1@4918.62,630 5025,630 J12.11@5045,650
PWM_SYNC: J2.2 J4.121 R9.2 R159.1 | length 1863
  Top Layer w8: R9.2@2080,2236.5 2183.5,2236.5 J2.2@2185,2235 2185,2305 2205,2325 2700,2325 2900,2125 3250,2125 3428.87,1946.13 v2(3428.87,1915) J4.121@3428.87,1860.93
  Bottom Layer w8: R159.1@3256.5,1865 3378.87,1865 v2(3428.87,1915)
PWM_SYNC_1: J4.140 R159.2 | length 225.3
  Top Layer w8: v2(3095,1775) 3130.41,1775 3145.41,1760 J4.140@3145.41,1727.07
  Bottom Layer w8: v2(3095,1775) 3103.5,1775 R159.2@3193.5,1865
PWM_SYNC_FPGA: J15.5 U20.30 | length 1045.6
  Top Layer w8: J15.5@2510,270 2510,320 2541.6,351.6 2820.98,351.6 2997.84,528.46 U20.30@3419.29,528.46
S0_CLK_GEN: J4.154 R86.1 U22.1 | length 1506.5
  Top Layer w8: R86.1@2111.5,1030 2154.23,987.26 v1(2160,987.26) 2167.1,980.16 U22.1@2209.76,980.16 ; v1(2895,1595) 2924.94,1624.94 J4.154@2924.93,1727.07
  Bottom Layer w8: v1(2160,987.26) 2280.26,987.26 2315,1022 2315,1420 2518,1623 2867,1623 v1(2895,1595)
S1_CLK_GEN: J4.156 R88.1 U22.2 | length 1438.2
  Top Layer w8: R88.1@2111.5,965 2129.03,947.46 v1(2160,947.46) 2167.1,954.57 U22.2@2209.76,954.57 ; v1(2820,1590) 2893.44,1663.44 J4.156@2893.44,1727.07
  Bottom Layer w8: v1(2160,947.46) 2277.46,947.46 2343,1013 2343,1398 2547.8,1602.8 2807.2,1602.8 v1(2820,1590)
SC_ALARM: J2.4 J4.123 | length 1403
  Top Layer w8: J2.4@2285,2235 2285,2290 2304.2,2309.2 2693.46,2309.2 2897.66,2105 3225,2105 3397.38,1932.62 J4.123@3397.38,1860.93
